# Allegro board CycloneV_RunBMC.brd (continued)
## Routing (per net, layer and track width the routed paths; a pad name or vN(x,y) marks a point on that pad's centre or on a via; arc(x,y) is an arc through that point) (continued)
V_M_BMC_DDR3_DQ<33>: length 39.8
  TOP w0.104: U4.F7 38.61,37.96 38.69,38.04 38.69,38.26 38.58,38.37 v1(37.74,38.37)
  TOP w0.127: UT7.U25 31.56,27.99 v1(31.56,28.01)
  L5-SIG w0.076: v1(31.56,28.01) 31.3,28.01 31.16,28.15 31.15,28.15 30.07,29.23 29.55,29.23 29.43,29.34 29.43,29.88 29.56,30 30.24,30 30.4,29.85 30.4,29.47 30.68,29.19 31.06,29.19 31.18,29.06 31.18,28.67 31.41,28.45 31.79,28.45 31.97,28.63 31.97,29.88 31.84,30 31.29,30 31.16,30.13 31.16,30.36 31.29,30.49 31.92,30.49 32.02,30.59 32.02,30.83 31.91,30.94 31.5,30.94 31.39,31.06 31.39,31.29 31.5,31.4 31.91,31.4 32.02,31.51 32.02,31.74 31.91,31.86 31.64,31.86 31.53,31.97 31.53,32.2 31.64,32.31 31.91,32.31 32.02,32.43 32.02,32.66 31.91,32.77 31.64,32.77 31.53,32.89 31.53,33.11 31.64,33.23 31.91,33.23 32.02,33.34 32.02,33.57 31.91,33.69 31.64,33.69 31.53,33.8 31.53,34.03 31.64,34.14 31.91,34.14 32.02,34.26 32.02,34.63 31.87,34.78 31.57,34.78 31.48,34.86 31.48,35.46 31.59,35.57 32.15,35.57 32.35,35.77 32.35,36.2 32.51,36.35 32.89,36.35 32.97,36.43 32.97,36.62 32.85,36.73 32.06,36.73 31.95,36.85 31.95,37.06 32.06,37.18 32.99,37.18 33.19,37.38 33.19,38.26 33.37,38.44 33.89,38.44 34,38.32 34,36.85 34.12,36.73 34.4,36.73 34.54,36.87 34.54,38.56 34.62,38.64 34.85,38.64 34.93,38.56 34.93,36.98 35.05,36.86 35.24,36.86 35.35,36.98 35.35,38.14 35.46,38.26 35.67,38.26 35.78,38.14 35.78,37.31 35.92,37.17 36.46,37.17 36.57,37.28 36.57,38.07 36.8,38.3 37.28,38.3 37.35,38.37 v1(37.74,38.37)
V_M_BMC_DDR3_DQ<34>: length 34
  TOP w0.127: v1(39.59,30.54) 39.26,30.87 36.3,30.87 35.98,30.54 UT7.AC28 ; U4.F2 v1(41.75,37.57)
  L5-SIG w0.076: v1(39.59,30.54) 39.24,30.89 36.04,30.89 35.93,30.99 35.93,31.25 36.06,31.37 39.82,31.37 40.1,31.65 40.1,32.57 40.71,33.18 40.71,35.16 39.87,36 39.87,36.86 40.3,37.29 40.58,37.29 41.41,36.47 41.64,36.47 41.78,36.61 41.78,36.89 40.76,37.9 40.76,41.83 40.87,41.94 42.02,41.94 42.13,41.83 42.13,41.27 42.02,41.15 41.41,41.15 41.29,41.04 41.29,38.03 v1(41.75,37.57)
V_M_BMC_DDR3_DQ<35>: length 38.9
  TOP w0.127: U4.F8 v1(36.95,37.56) ; v1(32.4,28.01) 32.38,28.01 UT7.V25
  L5-SIG w0.076: v1(36.95,37.56) 37.55,37.56 37.67,37.45 37.67,36.59 37.33,36.25 37.33,34.19 37.1,33.97 36.7,33.97 36.57,34.09 36.57,35.72 36.72,35.87 36.9,35.87 36.98,35.95 36.98,36.28 36.87,36.38 35.96,36.38 35.93,36.4 34.56,36.4 34.36,36.2 34.36,35.54 34.28,35.46 34.03,35.46 33.95,35.54 33.95,36.25 33.8,36.4 33.34,36.4 33.19,36.25 33.19,34.11 33.08,33.99 32.59,33.99 32.48,33.88 32.48,33.67 32.59,33.56 33.08,33.56 33.19,33.44 33.19,33.2 33.11,33.13 32.58,33.13 32.48,33.03 32.48,32.77 32.56,32.7 33.41,32.7 33.52,32.58 33.52,32.39 33.39,32.26 32.59,32.26 32.48,32.15 32.48,31.9 32.62,31.76 33.18,31.76 33.29,31.64 33.29,31.44 33.18,31.32 32.56,31.32 32.48,31.24 32.48,30.93 32.59,30.82 32.63,30.82 32.78,30.66 32.78,28.17 32.79,28.17 32.79,27.85 32.78,27.85 32.78,26.57 32.78,26.57 32.78,26.3 32.48,26 32.26,26 32.05,25.79 30.88,25.79 30.35,26.32 30.35,27.53 30.46,27.64 30.69,27.64 30.8,27.53 30.8,26.88 30.92,26.76 31.08,26.76 31.19,26.88 31.19,27.53 31.31,27.64 31.5,27.64 31.62,27.53 31.62,26.74 31.73,26.62 31.92,26.62 32,26.71 32,27.61 v1(32.4,28.01)
V_M_BMC_DDR3_DQ<36>: length 37.7
  TOP w0.127: U4.H3 v1(41.75,39.16) ; UT7.V19 32.36,23.19 v1(32.4,23.19)
  L5-SIG w0.076: v1(32.4,23.19) 32.77,22.81 33.34,22.81 33.6,23.08 33.6,25.21 34.38,25.99 34.38,26.55 34.68,26.85 34.93,26.85 35.14,27.06 35.14,27.3 35.43,27.59 36.59,27.59 36.75,27.74 36.75,28.22 36.92,28.4 39.59,28.4 39.92,28.73 42.41,28.73 43.77,30.09 43.77,32.89 44.29,33.41 44.29,35.44 45.26,36.4 45.26,41.88 45.14,41.99 44.56,41.99 44.44,42.11 44.44,42.79 44.33,42.91 44.1,42.91 43.98,42.79 43.98,42.11 43.87,41.99 43.06,41.99 42.94,41.88 42.94,40.57 42.72,40.34 42,40.34 41.75,40.08 v1(41.75,39.16)
V_M_BMC_DDR3_DQ<37>: length 37.6
  TOP w0.127: U4.H8 v1(37.75,39.97) ; UT7.V20 32.37,24 32.37,24.05 v1(32.38,24.05)
  L5-SIG w0.076: v1(37.75,39.97) 37.36,39.58 31.54,39.58 31.18,39.22 27.65,39.22 27.53,39.1 27.53,38.91 27.65,38.79 30.35,38.79 30.63,38.51 30.63,31.96 30.12,31.45 29.79,31.45 29.31,30.97 29.31,30.9 29.12,30.71 29.12,30.64 28.8,30.32 28.8,27.77 28.64,27.62 26.59,27.62 26.41,27.44 26.41,26.98 26.64,26.75 28.29,26.75 28.82,26.22 28.82,25.81 29.41,25.23 31.76,25.23 31.87,25.11 31.87,24.56 v1(32.38,24.05)
V_M_BMC_DDR3_DQ<38>: length 33.1
  TOP w0.127: UT7.AE27 v1(37.98,29.61) ; U4.G2 v1(42.55,38.36)
  L5-SIG w0.076: v1(37.98,29.61) 38.37,29.22 39.8,29.22 40.02,29.44 40.02,29.85 40.38,30.21 42.73,30.21 42.91,30.38 42.91,32.71 43.4,33.2 43.5,33.2 43.83,33.54 43.83,36.38 43.95,36.49 44.68,36.49 44.8,36.61 44.8,36.84 44.68,36.95 43.87,36.95 43.76,37.06 43.76,37.29 43.87,37.41 44.68,37.41 44.8,37.52 44.8,37.75 44.68,37.86 43.95,37.86 43.83,37.98 43.83,38.22 43.95,38.33 44.68,38.33 44.8,38.45 44.8,38.7 44.68,38.82 43.92,38.82 43.8,38.93 43.8,39.16 43.92,39.27 44.68,39.27 44.8,39.39 44.8,41.17 44.68,41.28 44.05,41.28 43.94,41.17 43.94,40.19 43.3,39.55 42.26,39.55 42.13,39.43 42.13,38.74 41.95,38.56 41.95,38.06 42.13,37.88 42.13,37.1 42.25,36.99 42.84,36.99 42.94,37.09 42.94,37.97 v1(42.55,38.36)
V_M_BMC_DDR3_DQ<39>: length 33.7
  TOP w0.127: U4.H7 39.53,39.56 39.74,39.35 v1(39.74,39.32) ; UT7.AD28 v1(36.37,30.41)
  L5-SIG w0.076: v1(39.74,39.32) 39.74,39.71 39.63,39.83 39.22,39.83 39.11,39.94 39.11,40.17 39.22,40.28 39.78,40.28 39.9,40.4 39.9,40.63 39.78,40.74 39.07,40.74 38.96,40.86 38.96,41.08 39.07,41.2 39.81,41.2 39.92,41.31 39.92,41.6 39.81,41.71 38.29,41.71 38.14,41.86 38.14,42.11 38.26,42.22 40.28,42.22 40.38,42.12 40.38,37.9 39.52,37.04 39.52,35.87 40.3,35.08 40.3,33.33 39.9,32.92 39.39,32.92 38.83,32.37 35.76,32.37 35.53,32.14 35.53,32.06 35.22,31.76 35.22,29.77 35.2,29.75 35.2,28.31 35.4,28.12 35.78,28.12 35.97,28.31 35.97,28.93 35.96,28.94 35.96,30 v1(36.37,30.41)
V_M_BMC_DDR3_DQS0_N: length 26.1
  TOP w0.127: U2.G3 v1(22.13,38.43) ; UT7.R16 29.91,20.74 29.91,20.79 v1(29.93,20.8)
  L3-SIG w0.076: v1(29.93,20.8) 29.95,20.99 29.88,21.08 29.86,21.09 29.48,21.09 29.46,21.09 28.62,21.92 25.77,21.92 25.51,22.18 25.51,24.41 25.39,24.53 25.39,25.84 24.56,26.68 23.2,26.68 22.3,27.57 22.3,29.45 22.32,29.47 22.32,29.75 21.53,30.54 21.53,30.69 21.47,30.75 21.46,30.75 21.44,30.76
  L3-SIG w0.099: v1(22.13,38.43) 21.91,38.21 21.5,38.21 20.69,37.4 20.69,32.19 21.44,31.44 21.44,30.76
V_M_BMC_DDR3_DQS0_P: length 26.4
  TOP w0.127: UT7.R17 v1(29.99,21.62) ; U2.F3 v1(22.13,37.63)
  L3-SIG w0.076: 21.68,30.76 21.68,30.6 22.47,29.81 22.47,29.4 22.45,29.38 22.45,27.63 23.26,26.83 24.62,26.83 25.55,25.9 25.55,24.59 25.75,24.39 25.75,24.16 25.66,24.07 25.66,23.87 25.77,23.75 25.77,23.48 25.66,23.36 25.66,23.04 25.77,22.93 25.77,22.68 25.66,22.56 25.66,22.24 25.83,22.07 26.2,22.07 26.31,22.18 26.54,22.18 26.64,22.07 26.94,22.07 27.04,22.18 27.3,22.18 27.41,22.07 27.78,22.07 27.89,22.18 28.14,22.18 28.24,22.07 28.83,22.07 28.94,21.96 28.94,21.82 29.1,21.66 29.16,21.66 29.22,21.66 29.36,21.51 29.36,21.46 29.36,21.46 29.36,21.4 29.51,21.25 29.55,21.25 29.92,21.25 29.97,21.3 v1(29.99,21.62)
  L3-SIG w0.099: v1(22.13,37.63) 22.13,37.84 22.02,37.95 21.61,37.95 20.95,37.29 20.95,32.29 21.68,31.56 21.68,30.76
V_M_BMC_DDR3_DQS1_N: length 21.1
  TOP w0.127: v1(29.97,22.4) UT7.R18 ; U2.B7 v1(18.93,34.43)
  L5-SIG w0.076: 25.46,30.76 25.46,30.75 25.5,30.71 25.5,26.95 26.51,25.94 27.81,25.94 29.13,24.62 29.13,23.07 29.49,22.71 29.66,22.71 29.66,22.71 v1(29.97,22.4)
  L5-SIG w0.094: v1(18.93,34.43) 19.21,34.71 19.38,34.71 19.5,34.58 19.5,34.07 22.1,31.48 25.2,31.48 25.46,31.21 25.46,30.76
V_M_BMC_DDR3_DQS1_P: length 21.3
  TOP w0.127: v1(29.97,23.16) 29.62,22.81 UT7.R19 ; U2.C7 v1(18.93,35.23)
  L5-SIG w0.076: v1(29.97,23.16) 29.97,22.97 29.86,22.86 29.65,22.86 29.55,22.86 29.28,23.13 29.28,24.68 27.87,26.09 26.57,26.09 25.66,27.01 25.66,30.71 25.69,30.75 25.69,30.76
  L5-SIG w0.094: v1(18.93,35.23) 19.22,34.93 19.47,34.93 19.73,34.68 19.73,34.17 22.19,31.7 25.3,31.7 25.69,31.31 25.69,30.76
V_M_BMC_DDR3_DQS2_N: length 27.3
  TOP w0.127: U3.G3 v1(31.19,38.43) ; UT7.T18 v1(30.78,22.41)
  L10-SIG w0.076: v1(30.78,22.41) 30.78,22.49 30.63,22.64 30.51,22.64 30.32,22.83 30.32,23.3 30.12,23.5 29.52,23.5 29.29,23.73 29.29,23.8
  L10-SIG w0.099: 29.29,23.8 29.29,33.49 29.57,33.78 31.37,33.78 31.51,33.91 31.51,34.3 31.4,34.41 29.49,34.41 29.23,34.67 29.23,35.11 29.49,35.37 31.25,35.37 31.36,35.48 31.36,35.7 31.25,35.82 29.62,35.82 29.36,36.08 29.36,36.51 29.62,36.77 30.06,36.77 30.17,36.88 30.17,38.01 30.47,38.31 31.08,38.31 v1(31.19,38.43)
V_M_BMC_DDR3_DQS2_P: length 28.1
  TOP w0.127: UT7.T19 v1(30.78,23.21) ; U3.F3 v1(31.19,37.63)
  L10-SIG w0.076: v1(30.78,23.21) 30.78,22.89 30.68,22.79 30.57,22.79 30.47,22.89 30.47,23.44 30.26,23.65 29.58,23.65 29.54,23.7 29.54,23.8
  L10-SIG w0.099: v1(31.19,37.63) 31.19,37.89 31.03,38.05 30.57,38.05 30.42,37.9 30.42,36.78 30.16,36.52 29.72,36.52 29.61,36.4 29.61,36.18 29.72,36.07 31.36,36.07 31.62,35.81 31.62,35.37 31.36,35.11 29.59,35.11 29.48,35 29.48,34.78 29.59,34.67 31.5,34.67 31.76,34.41 31.76,33.81 31.48,33.52 29.68,33.52 29.54,33.38 29.54,31.22 29.71,31.04 29.71,30.69 29.54,30.52 29.54,30.22 29.66,30.1 29.66,29.87 29.54,29.75 29.54,29.44 29.66,29.32 29.66,29.04 29.54,28.92 29.54,28.65 29.66,28.53 29.66,28.29 29.54,28.17 29.54,27.84 29.71,27.67 29.71,27.49 29.54,27.32 29.54,27.05 29.66,26.93 29.66,26.65 29.54,26.53 29.54,25.73 29.71,25.56 29.71,25.25 29.54,25.08 29.54,24.79 29.74,24.59 29.74,24.31 29.54,24.12 29.54,23.8
V_M_BMC_DDR3_DQS3_N: length 29.9
  TOP w0.119: U3.B7 v1(28.91,35.34)
  TOP w0.127: UT7.T20 v1(30.78,24.01)
  L3-SIG w0.076: v1(30.78,24.01) 30.78,23.63 30.85,23.55 31.01,23.55 31.08,23.63 31.08,24.39 31.23,24.54 31.39,24.54 31.52,24.66 31.52,24.83 31.66,24.97 31.83,24.97 31.9,25.04 31.9,25.2 31.82,25.28 31.27,25.28 31.11,25.44 31.11,25.8 31.27,25.96 31.71,25.96 31.83,26.09 31.83,26.74 31.72,26.85 31.28,26.85 31.09,27.04 31.09,27.28 31.43,27.62 31.82,27.62 31.9,27.69 31.9,30.51 31.74,30.67 31.53,30.67
  L3-SIG w0.099: v1(28.91,35.34) 28.91,35.65 28.99,35.73 29.44,35.73 29.84,36.12 30.47,36.12 30.6,36 31.25,36 31.36,35.89 31.36,35.5 31.23,35.36 29.57,35.36 29.31,35.1 29.31,34.56 29.57,34.3 31.61,34.3 31.72,34.18 31.72,33.83 31.61,33.72 30.15,33.72 29.89,33.46 29.89,32.77 30.15,32.51 31.93,32.51 32.05,32.39 32.05,32.06 31.93,31.94 30.96,31.94 30.65,31.63 30.65,31.05 31.02,30.67 31.53,30.67
V_M_BMC_DDR3_DQS3_P: length 29.5
  TOP w0.127: U3.C7 28.87,36.1 v1(28.9,36.1) ; v1(31.56,23.21) 31.56,23.19 UT7.U19
  L3-SIG w0.076: 31.96,30.76 32.05,30.67 32.05,27.63 31.89,27.46 31.49,27.46 31.24,27.21 31.24,27.1 31.34,27.01 31.78,27.01 31.98,26.8 31.98,26.03 31.77,25.81 31.34,25.81 31.26,25.74 31.26,25.51 31.34,25.43 31.89,25.43 32.05,25.27 32.05,24.98 31.24,24.16 31.24,23.53 v1(31.56,23.21)
  L3-SIG w0.099: 31.96,30.76 31.8,30.93 31.13,30.93 30.91,31.15 30.91,31.53 31.07,31.69 32.03,31.69 32.3,31.96 32.3,32.49 32.03,32.76 30.25,32.76 30.14,32.87 30.14,33.35 30.25,33.46 31.71,33.46 31.97,33.72 31.97,34.29 31.71,34.55 29.68,34.55 29.56,34.66 29.56,35 29.68,35.11 31.33,35.11 31.62,35.39 31.62,35.99 31.36,36.25 30.71,36.25 30.58,36.38 29.73,36.38 29.34,35.98 29.06,35.98 28.95,36.1 v1(28.9,36.1)
V_M_BMC_DDR3_DQS4_N: length 37.7
  TOP w0.127: v1(39.77,38.76) 40.02,38.51 41.1,38.51 U4.G3 ; UT7.V17 v1(32.38,21.61)
  L5-SIG w0.076: v1(32.38,21.61) 32.34,21.61 31.9,22.05 31.9,23.52 32.07,23.68 32.49,23.68 32.72,23.91 32.72,25.26 33.5,26.04 33.5,26.9 33.5,26.91 33.5,29.37 33.71,29.58 34.18,29.58 34.26,29.66 34.26,29.81 34.18,29.89 33.66,29.89 33.5,30.05 33.5,30.71 33.46,30.75 33.46,30.76
  L5-SIG w0.094: 33.46,30.76 33.46,30.95 34.82,32.31 34.82,32.56 34.69,32.68 34.19,32.68 33.93,32.94 33.93,33.36 34.19,33.62 34.69,33.62 34.82,33.75 34.82,33.99 34.69,34.11 34.29,34.11 34.03,34.37 34.03,34.8 34.29,35.06 34.69,35.06 34.82,35.18 34.82,35.68 35.07,35.94 35.48,35.94 35.73,35.68 35.73,33.42 35.98,33.18 37.68,33.18 37.68,33.18 38.05,33.18 38.17,33.3 38.17,33.7 38.43,33.95 39.5,33.95 39.62,34.08 39.62,34.32 39.5,34.44 38.43,34.44 38.17,34.7 38.17,35.13 38.43,35.39 38.71,35.39 38.83,35.51 38.83,35.75 38.71,35.87 38.43,35.87 38.17,36.13 38.17,37.92 38.71,38.46 39.47,38.46 v1(39.77,38.76)
V_M_BMC_DDR3_DQS4_P: length 37.6
  TOP w0.127: U4.F3 41.06,38.25 40.05,38.25 v1(39.77,37.96) ; UT7.V18 v1(32.38,22.41)
  L5-SIG w0.076: v1(32.38,22.41) 32.38,22.15 32.28,22.05 32.11,22.05 32.05,22.11 32.05,22.62 32.15,22.71 32.15,22.92 32.05,23.02 32.05,23.45 32.13,23.53 32.56,23.53 32.87,23.85 32.87,24.22 32.99,24.34 32.99,24.57 32.87,24.68 32.87,25.2 33.05,25.38 33.22,25.38 33.37,25.53 33.37,25.7 33.65,25.98 33.65,26.68 33.75,26.77 33.75,27 33.65,27.1 33.65,29.31 33.78,29.43 34.25,29.43 34.41,29.6 34.41,29.88 34.25,30.04 33.73,30.04 33.65,30.12 33.65,30.71 33.69,30.75 33.69,30.76
  L5-SIG w0.094: v1(39.77,37.96) 39.77,38.05 39.59,38.23 38.8,38.23 38.4,37.83 38.4,36.22 38.52,36.1 38.8,36.1 39.06,35.85 39.06,35.41 38.8,35.16 38.52,35.16 38.4,35.04 38.4,34.79 38.52,34.67 39.59,34.67 39.85,34.41 39.85,33.98 39.59,33.73 38.52,33.73 38.4,33.6 38.4,33.2 38.14,32.95 37.59,32.95 37.58,32.95 35.88,32.95 35.5,33.33 35.5,35.59 35.38,35.71 35.17,35.71 35.05,35.59 35.05,35.08 34.79,34.83 34.38,34.83 34.26,34.71 34.26,34.46 34.38,34.34 34.79,34.34 35.05,34.08 35.05,33.65 34.79,33.39 34.29,33.39 34.16,33.26 34.16,33.04 34.29,32.91 34.79,32.91 35.05,32.65 35.05,32.21 33.69,30.86 33.69,30.76
V_M_BMC_DDR3_MA<0>: length 51.6
  TOP w0.127: U3.N3 v1(31.97,44.01) ; v1(19.6,30.71) 19.6,30.38 UT7.C28 ; U4.N3 v1(41.75,43.96) ; U2.N3 v1(22.13,44.03)
  L8-SIG w0.076: v1(19.6,30.71) 19.6,31.1 19.42,31.28 19.42,31.88 20.52,32.97 20.52,33.49 20.4,33.61 19.87,33.61 19.75,33.72 19.75,33.95 19.87,34.06 20.4,34.06 20.52,34.18 20.52,34.41 20.4,34.52 19.87,34.52 19.75,34.64 19.75,34.86 19.87,34.98 20.4,34.98 20.52,35.09 20.52,35.32 20.4,35.44 19.87,35.44 19.75,35.55 19.75,35.78 19.87,35.89 20.4,35.89 20.52,36.01 20.52,36.43 20.63,36.54 20.83,36.54 20.95,36.65 20.95,36.88 20.83,37 20.63,37 20.52,37.11 20.52,37.34 20.63,37.45 20.99,37.45 21.1,37.57 21.1,37.8 20.99,37.91 20.63,37.91 20.52,38.03 20.52,38.25 20.63,38.37 21.11,38.37 21.23,38.48 21.23,38.71 21.11,38.83 20.63,38.83 20.52,38.94 20.52,39.17 20.63,39.28 21.11,39.28 21.23,39.4 21.23,39.63 21.11,39.74 20.63,39.74 20.52,39.85 20.52,40.08 20.63,40.2 20.83,40.2 20.95,40.31 20.95,40.54 20.83,40.65 20.63,40.65 20.52,40.77 20.52,41 20.63,41.11 20.73,41.11 20.85,41.23 20.85,41.45 20.73,41.57 20.63,41.57 20.52,41.68 20.52,41.91 20.63,42.03 20.71,42.03 20.82,42.14 20.82,42.37 20.71,42.48 20.63,42.48 20.52,42.6 20.52,43.72 20.95,44.15 22,44.15 v1(22.13,44.03) 22.55,43.6 23.88,43.6 23.89,43.59 31.56,43.59 v1(31.97,44.01) 32.39,43.59 41.37,43.59 v1(41.75,43.96)
  BOTTOM w0.112: RB4.1 41.62,47.58 41.16,47.12 41.16,44.55 v1(41.75,43.96)
V_M_BMC_DDR3_MA<1>: length 51.3
  TOP w0.127: U2.P7 v1(18.13,44.83) ; UT7.B28 18.78,30.41 18.78,30.68 v1(18.77,30.69) ; U3.P7 v1(27.97,44.81) ; U4.P7 v1(37.75,44.76)
  L10-SIG w0.076: v1(37.75,44.76) 37.34,44.35 33.74,44.35 33.72,44.37 31.82,44.37 31.81,44.35 28.42,44.35 v1(27.97,44.81) 27.56,44.39 19.49,44.39 19.05,44.83 v1(18.13,44.83) 18.13,44.83 17.84,44.83 17.42,45.24 16.35,45.24 15.51,44.4 15.51,40.16 15.97,39.71 18.31,39.71 18.51,39.5 18.51,37.3 18.6,37.21 20.12,37.21 20.21,37.12 20.21,36.94 20.12,36.85 18.6,36.85 18.51,36.76 18.51,33.85 18.77,33.59 18.77,33.37 18.86,33.28 19.23,33.28 19.32,33.2 19.32,33.02 19.23,32.93 18.86,32.93 18.69,32.76 18.69,30.77 v1(18.77,30.69)
  BOTTOM w0.112: RB12.1 37.05,47.91 37.7,47.26 38.06,47.26 38.57,46.75 38.59,46.75 38.8,46.54 38.8,45.82 v1(37.75,44.76)
V_M_BMC_DDR3_MA<2>: length 52.6
  TOP w0.127: U2.P3 v1(22.13,44.83) ; UT7.E26 v1(21.18,28.81) ; U4.P3 v1(41.75,44.76) ; U3.P3 v1(31.97,44.81)
  L8-SIG w0.076: v1(21.18,28.81) 20.98,28.81 20.54,29.24 20.11,29.24 19.96,29.39 19.96,29.95 19.75,30.16 19.36,30.16 19.14,30.37 19.14,30.89 18.87,31.17 18.87,32.77 19.37,33.28 19.37,36.77 19.49,36.88 19.92,36.88 20.03,37 20.03,37.23 19.92,37.34 19.69,37.34 19.58,37.45 19.58,37.68 19.69,37.8 19.92,37.8 20.03,37.91 20.03,38.14 19.92,38.25 19.44,38.25 19.32,38.37 19.32,38.6 19.44,38.71 19.92,38.71 20.03,38.83 20.03,39.05 19.92,39.17 19.41,39.17 19.3,39.28 19.3,39.51 19.41,39.63 19.92,39.63 20.03,39.74 20.03,39.97 19.92,40.08 19.28,40.08 19.17,40.2 19.17,40.43 19.28,40.54 19.92,40.54 20.03,40.65 20.03,40.88 19.92,41 19.56,41 19.45,41.11 19.45,41.34 19.56,41.45 19.92,41.45 20.03,41.57 20.03,41.8 19.92,41.91 19.69,41.91 19.58,42.03 19.58,42.25 19.69,42.37 19.92,42.37 20.03,42.48 20.03,42.71 19.92,42.83 19.69,42.83 19.58,42.94 19.58,43.26 21.14,44.83 v1(22.13,44.83) 22.52,44.43 31.6,44.43 v1(31.97,44.81) 32.4,44.38 41.4,44.38 41.75,44.73 v1(41.75,44.76)
  BOTTOM w0.112: v1(41.75,44.76) 41.39,45.12 41.39,45.41 41.39,45.41 41.39,46.89 42.13,47.63 RB3.1
V_M_BMC_DDR3_MA<3>: length 49.7
  TOP w0.127: U2.N2 v1(22.93,44.03) ; U3.N2 v1(32.77,44.01) ; UT7.D26 v1(20.38,28.81) ; U4.N2 v1(42.55,43.96)
  L3-SIG w0.076: v1(42.55,43.96) 42.16,44.35 33.12,44.35 v1(32.77,44.01) 32.4,44.38 23.28,44.38 v1(22.93,44.03)
  BOTTOM w0.112: v1(20.38,28.81) 20.75,29.17 20.75,30.18 20.49,30.43 20.49,31.76 20.95,32.21 20.95,33.31 20.79,33.46 19.99,33.46 19.88,33.57 19.88,33.77 19.99,33.88 20.79,33.88 20.9,33.98 20.9,34.19 20.79,34.3 19.99,34.3 19.88,34.4 19.88,34.61 19.99,34.71 20.79,34.71 20.9,34.82 20.9,39.06 21,39.17 21.28,39.17 21.38,39.27 21.38,39.48 21.28,39.58 20.82,39.58 20.72,39.69 20.72,39.9 20.82,40 21.28,40 21.38,40.1 21.38,40.31 21.28,40.42 20.82,40.42 20.72,40.52 20.72,40.73 20.82,40.83 21.28,40.83 21.38,40.94 21.38,41.15 21.28,41.25 20.87,41.25 20.77,41.35 20.77,41.56 20.87,41.67 21.28,41.67 21.38,41.77 21.38,41.98 21.28,42.08 21,42.08 20.9,42.19 20.9,43.41 21.1,43.62 22.52,43.62 v1(22.93,44.03) ; v1(42.55,43.96) 42.92,43.59 43.14,43.59 43.17,43.57 RB37.1
V_M_BMC_DDR3_MA<4>: length 56.3
  TOP w0.127: U2.P8 v1(17.33,44.83) ; U4.P8 v1(36.95,44.76) ; U3.P8 v1(27.17,44.81) ; UT7.J21 v1(24.38,24.81)
  L5-SIG w0.076: v1(24.38,24.81) 24.29,24.81 23.9,25.2 18.61,25.2 17.73,26.09 17.72,26.09 17.51,26.3 17.51,26.3 14.73,29.09 14.73,42.96 16.23,44.47 16.96,44.47 v1(17.33,44.83) 17.72,44.43 26.8,44.43 v1(27.17,44.81)
  L5-SIG w0.114: v1(27.17,44.81) 27.53,44.44 35.72,44.44 35.76,44.4 36.59,44.4 v1(36.95,44.76)
  BOTTOM w0.112: RB17.1 34,47.4 34.79,46.61 34.79,45.9 35.34,45.34 35.34,45.34 35.43,45.25 35.44,45.25 35.5,45.18 36.53,45.18 v1(36.95,44.76)
V_M_BMC_DDR3_MA<5>: length 51.1
  TOP w0.127: UT7.J20 v1(24.38,24.01) ; U2.P2 v1(22.93,44.83) ; U4.P2 v1(42.55,44.76) ; U3.P2 v1(32.77,44.81)
  L5-SIG w0.076: v1(22.93,44.83) 23.34,45.24 32.33,45.24 v1(32.77,44.81) 33.21,45.24 35.96,45.24 36,45.2 42.11,45.2 v1(42.55,44.76)
  BOTTOM w0.112: v1(42.55,44.76) 42.94,45.16 44.07,45.16 44.57,44.66 RB32.1 ; v1(24.38,24.01) 24,24.39 24,26.09 23.08,27.01 23.08,27.67 23.18,27.77 23.18,29.19 21.38,30.99 21.38,32.21 21.81,32.64 22.75,32.64 22.85,32.75 22.85,32.96 22.75,33.06 21.81,33.06 21.71,33.16 21.71,42.6 21.96,42.86 23.16,42.86 23.31,43.01 23.31,44.44 v1(22.93,44.83)
V_M_BMC_DDR3_MA<6>: length 50.6
  TOP w0.127: U4.R8 v1(36.95,45.56) ; U3.R8 v1(27.17,45.61) ; UT7.C26 v1(19.58,28.81) ; U2.R8 v1(17.33,45.63)
  L10-SIG w0.076: v1(36.95,45.56) 36.59,45.2 27.58,45.2 v1(27.17,45.61) 26.76,45.19 21.87,45.19 21.81,45.24 17.87,45.24 17.49,45.63 v1(17.33,45.63) 16.96,45.99 16.13,45.99 15.13,44.99 15.13,39.81 16.07,38.87 17.65,38.87 17.77,38.74 17.77,38.47 17.68,38.38 17.02,38.38 16.94,38.29 16.94,38.11 17.02,38.02 17.68,38.02 17.77,37.93 17.77,29.55 18.1,29.22 19.48,29.22 19.58,29.11 v1(19.58,28.81)
  BOTTOM w0.112: RB16.1 34.51,47.53 35.32,46.73 36.3,46.73 36.57,46.45 36.57,45.94 v1(36.95,45.56)
V_M_BMC_DDR3_MA<7>: length 51.1
  TOP w0.127: UT7.B26 18.8,28.79 v1(18.8,28.83) ; U3.R2 v1(32.77,45.61) ; U4.R2 v1(42.55,45.56) ; U2.R2 v1(22.93,45.63)
  L8-SIG w0.076: v1(42.55,45.56) 42.17,45.19 33.19,45.19 v1(32.77,45.61) 32.4,45.23 23.32,45.23 v1(22.93,45.63) 22.54,45.24 19.78,45.24 19.28,44.75 19.28,44.59 19.72,44.15 19.72,43.99 19.56,43.83 19.4,43.83 18.96,44.26 18.8,44.26 18.51,43.97 18.51,42.07 18.4,41.95 18.09,41.95 17.98,41.84 17.98,41.61 18.09,41.49 18.4,41.49 18.51,41.38 18.51,41.15 18.4,41.04 18.09,41.04 17.98,40.92 17.98,40.69 18.09,40.58 18.4,40.58 18.51,40.47 18.51,34.09 18.84,33.76 18.84,33.53 18.33,33.03 18.33,30.46 18.61,30.18 18.84,30.18 19.2,29.83 19.2,29.01 19.01,28.83 v1(18.8,28.83)
  BOTTOM w0.112: v1(42.55,45.56) 42.97,45.98 42.97,46.49 42.99,46.51 42.99,46.51 43.2,46.73 43.2,46.73 43.25,46.77 43.95,46.77 44.11,46.61 44.11,45.88 44.8,45.19 RB30.1
V_M_BMC_DDR3_MA<8>: length 56
  TOP w0.127: U3.T8 v1(27.17,46.41) ; UT7.F26 21.98,28.81 v1(21.96,28.81) ; U4.T8 v1(36.95,46.36) ; U2.T8 v1(17.33,46.43)
  L10-SIG w0.076: v1(21.96,28.81) 21.6,28.45 17.12,28.45 16.76,28.81 16.76,29.72 17.37,30.33 17.37,36.91 17.04,37.24 14.9,37.24 14.78,37.37 14.78,38 14.87,38.09 15.58,38.09 15.67,38.18 15.67,38.36 15.58,38.45 14.87,38.45 14.78,38.53 14.78,38.71 14.87,38.8 15.25,38.8 15.33,38.89 15.33,39.07 15.25,39.16 14.87,39.16 14.78,39.25 14.78,45.34 16.33,46.89 16.86,46.89 v1(17.33,46.43) 17.75,46 26.77,46 v1(27.17,46.41) 27.61,45.97 36.55,45.97 v1(36.95,46.36)
  BOTTOM w0.112: v1(36.95,46.36) 36.95,46.46 36.47,46.94 35.74,46.94 35.02,47.66 RB15.1
V_M_BMC_DDR3_MA<9>: length 55.6
  TOP w0.127: UT7.F25 v1(21.96,28.03) ; U2.R3 v1(22.13,45.63) ; U4.R3 v1(41.75,45.56) ; U3.R3 v1(31.97,45.61)
  L8-SIG w0.076: v1(21.96,28.03) 21.58,28.4 19.97,28.4 19.86,28.29 19.86,27.9 19.76,27.8 19.42,27.8 19.32,27.9 19.32,28.29 19.21,28.4 18.56,28.4 18.36,28.61 18.36,29.75 17.89,30.22 17.89,33.04 17.72,33.2 17.72,34.18 17.61,34.3 17.41,34.3 17.29,34.41 17.29,34.64 17.41,34.75 17.66,34.75 17.77,34.87 17.77,35.1 17.66,35.21 17.41,35.21 17.29,35.32 17.29,35.55 17.41,35.67 17.61,35.67 17.72,35.78 17.72,36.01 17.61,36.12 17.41,36.12 17.29,36.24 17.29,36.47 17.41,36.58 17.61,36.58 17.72,36.7 17.72,36.92 17.61,37.04 17.41,37.04 17.29,37.15 17.29,37.38 17.41,37.5 17.61,37.5 17.72,37.61 17.72,37.84 17.61,37.95 17.41,37.95 17.29,38.07 17.29,38.3 17.41,38.41 17.61,38.41 17.72,38.52 17.72,38.75 17.61,38.87 17.41,38.87 17.29,38.98 17.29,39.21 17.41,39.32 17.61,39.32 17.72,39.44 17.72,39.67 17.61,39.78 17.41,39.78 17.29,39.9 17.29,40.12 17.41,40.24 17.61,40.24 17.72,40.35 17.72,44.18 17.98,44.43 18.38,44.43 19.58,45.63 v1(22.13,45.63) 22.5,46 31.57,46 v1(31.97,45.61) 32.37,46 35.99,46 36,46 41.31,46 v1(41.75,45.56)
  BOTTOM w0.112: v1(41.75,45.56) 42.13,45.95 42.13,46.51 43.27,47.66 RB1.1
V_M_BMC_DDR3_MA<10>: length 52.6
  TOP w0.127: U2.L7 v1(18.13,42.43) ; U3.L7 v1(27.97,42.41) ; U4.L7 v1(37.75,42.36) ; UT7.A24 v1(17.98,27.21)
  L5-SIG w0.076: v1(18.13,42.43) 21.43,42.43 21.81,42.04 27.61,42.04 v1(27.97,42.41) 28.46,42.41 28.87,41.99 37.38,41.99 v1(37.75,42.36)
  BOTTOM w0.112: RB8.1 39.08,47.61 39.62,47.07 39.62,46.93 39.68,46.87 39.68,43.5 38.54,42.36 v1(37.75,42.36) ; v1(17.98,27.21) 17.54,27.64 17.54,29.01 17.98,29.44 17.98,30.64 17.72,30.89 17.72,32.13 17.62,32.23 17.24,32.23 17.14,32.33 17.14,32.54 17.24,32.65 17.62,32.65 17.72,32.75 17.72,32.96 17.62,33.06 17.24,33.06 17.14,33.17 17.14,33.38 17.24,33.48 17.62,33.48 17.72,33.58 17.72,37.08 17.86,37.22 19.45,37.22 19.55,37.32 19.55,39.8 19.45,39.9 18.39,39.9 18.28,40.01 18.28,40.21 18.39,40.32 19.45,40.32 19.55,40.42 19.55,42.19 19.14,42.6 18.3,42.6 v1(18.13,42.43)
V_M_BMC_DDR3_MA<11>: length 49.6
  TOP w0.127: U4.R7 v1(37.75,45.56) ; UT7.B24 v1(18.78,27.21) ; U2.R7 v1(18.13,45.63) ; U3.R7 v1(27.97,45.61)
  L3-SIG w0.076: v1(37.75,45.56) 37.4,45.22 37.09,45.22 37.09,45.22 36,45.22 36,45.22 28.36,45.22 v1(27.97,45.61) 27.62,45.26 21.87,45.26 21.5,45.63 v1(18.13,45.63)
  BOTTOM w0.112: v1(37.75,45.56) 37.33,45.98 37.33,46.48 37.31,46.5 37.31,46.51 37.1,46.73 36.99,46.73 36.56,47.15 36.01,47.15 35.53,47.63 RB14.1 ; v1(18.13,45.63) 18.22,45.73 19.7,45.73 19.91,45.52 19.91,45.28 19.8,45.18 19.3,45.18 19.2,45.07 19.2,44.86 19.3,44.76 19.8,44.76 19.91,44.66 19.91,44.45 19.8,44.34 19.58,44.34 19.48,44.24 19.48,44.03 19.58,43.93 19.8,43.93 19.91,43.82 19.91,37.14 19.53,36.76 18.69,36.76 18.54,36.61 18.54,33.43 18.36,33.25 18.36,27.63 v1(18.78,27.21)
V_M_BMC_DDR3_MA<12>: length 56.1
  TOP w0.127: v1(20.38,27.19) 20.4,27.19 UT7.D24 ; U4.N7 v1(37.75,43.96) ; U2.N7 v1(18.13,44.03) ; U3.N7 v1(27.97,44.01)
  L3-SIG w0.076: v1(20.38,27.19) 20.44,27.25 20.44,27.59 20.73,27.88 20.73,28.97 20.53,29.17 19.33,29.17 19.17,29.01 19.17,28.53 19.04,28.4 18.66,28.4 18.38,28.12 18.38,27.84 18.15,27.62 17.19,27.62 16.83,27.97 16.83,29.58 16.66,29.75 16.66,29.75 16.58,29.83 16.58,30.94 16.1,31.43 16.1,32.8 15.31,33.58 15.31,35.78 15.4,35.87 15.73,35.87 15.82,35.96 15.82,36.14 15.73,36.23 15.4,36.23 15.31,36.31 15.31,36.49 15.4,36.58 15.73,36.58 15.82,36.67 15.82,36.85 15.73,36.94 15.4,36.94 15.31,37.03 15.31,37.2 15.4,37.29 15.73,37.29 15.82,37.38 15.82,37.56 15.73,37.65 15.4,37.65 15.31,37.74 15.31,42.7 16.2,43.59 17.69,43.59 v1(18.13,44.03) 21.55,44.03 21.94,43.64 27.61,43.64 v1(27.97,44.01) 31.23,44.01 31.64,43.59 37.38,43.59 v1(37.75,43.96)
  BOTTOM w0.112: RB10.1 38.07,47.9 38.36,47.6 38.36,47.59 39.19,46.76 39.19,46.75 39.23,46.72 39.23,45.23 37.96,43.96 v1(37.75,43.96)
V_M_BMC_DDR3_MA<13>: length 52
  TOP w0.127: U3.T3 v1(31.97,46.41) ; U4.T3 v1(41.75,46.36) ; U2.T3 v1(22.13,46.43) ; UT7.C24 v1(19.58,27.21)
  L5-SIG w0.076: v1(41.75,46.36) 41.36,45.98 32.4,45.98 v1(31.97,46.41) 31.6,46.03 22.52,46.03 v1(22.13,46.43)
  L8-SIG w0.076: v1(19.58,27.21) 19.2,27.59 17.72,27.59 17.01,28.3 17.01,29.67 17.44,30.1 17.44,32.8 16.93,33.31 16.93,45.09 17.06,45.22 18.48,45.22 19.69,46.43 20.28,46.43 20.36,46.35 20.36,46.06 20.43,45.98 20.59,45.98 20.66,46.06 20.66,46.35 20.74,46.43 20.89,46.43 20.97,46.35 20.97,46.06 21.04,45.98 21.2,45.98 21.27,46.06 21.27,46.35 21.35,46.43 v1(22.13,46.43)
  BOTTOM w0.112: RB2.1 42.64,47.61 41.75,46.71 v1(41.75,46.36)
V_M_BMC_DDR3_MA<14>: length 55.6
  TOP w0.127: U4.T7 v1(37.75,46.36) ; U3.T7 v1(27.97,46.41) ; U2.T7 v1(18.13,46.43) ; UT7.G23 v1(23.58,25.6)
  L3-SIG w0.076: v1(18.13,46.43) 18.5,46.06 27.62,46.06 v1(27.97,46.41) 28.36,46.02 37.4,46.02 v1(37.75,46.36)
  BOTTOM w0.112: v1(37.75,46.36) 37.52,46.59 37.52,46.6 36.78,47.35 36.69,47.35 36.67,47.37 36.37,47.37 36.04,47.7 RB13.1 ; v1(18.13,46.43) 18.52,46.82 19.84,46.82 20.34,46.32 20.34,36.96 19.35,35.97 19.35,35.74 19.45,35.64 20.01,35.64 20.11,35.53 20.11,35.32 20.01,35.22 19.45,35.22 19.35,35.12 19.35,33.91 19.02,33.58 19.02,33.01 19.12,32.9 19.52,32.9 19.63,32.8 19.63,32.59 19.52,32.49 19.12,32.49 19.02,32.38 19.02,32.18 19.12,32.07 19.5,32.07 19.6,31.97 19.6,31.76 19.5,31.65 19.12,31.65 19.02,31.55 19.02,31.21 19.12,31.11 19.77,31.11 19.98,30.89 19.98,28.56 20.14,28.4 22.19,28.4 22.35,28.25 22.35,27.34 23.58,26.1 v1(23.58,25.6)
V_M_BMC_DDR3_MA<15>: length 59.8
  TOP w0.127: UT7.F24 22,27.19 v1(21.96,27.19) ; v1(38.55,43.19) 38.55,43.16 U4.M7 ; U3.M7 v1(28.77,43.21) ; U2.M7 v1(18.93,43.23)
  L10-SIG w0.076: v1(38.55,43.19) 38.13,42.77 31.82,42.77 31.76,42.7 29.27,42.7 v1(28.77,43.21) 28.4,42.83 19.32,42.83 v1(18.93,43.23) 18.56,43.59 17.43,43.59 17.35,43.5 17.35,43.27 17.26,43.19 17.08,43.19 16.99,43.27 16.99,43.5 16.9,43.59 16.35,43.59 16.15,43.39 16.15,40.65 16.38,40.42 17.68,40.42 17.76,40.51 17.76,40.86 17.85,40.95 18.03,40.95 18.12,40.86 18.12,40.51 18.21,40.42 19.35,40.42 19.44,40.51 19.44,40.79 19.53,40.87 19.71,40.87 19.8,40.79 19.8,40.51 19.89,40.42 20.82,40.42 20.92,40.32 20.92,31.73 21.23,31.43 23.84,31.43 24.02,31.25 24.02,26.75 23.89,26.62 23.29,26.62 23.08,26.83 22.32,26.83 v1(21.96,27.19)
  BOTTOM w0.112: v1(38.55,43.19) 38.55,43.96 39.44,44.86 39.44,46.81 39.41,46.84 39.41,46.85 38.58,47.68 RB9.1
V_M_BMC_DDR3_ODT: length 47.7
  TOP w0.127: UT7.D28 20.78,30.49 v1(21,30.71) ; U3.K1 v1(33.57,41.61) ; U2.K1 v1(23.73,41.63) ; U4.K1 v1(43.35,41.56)
  L8-SIG w0.076: v1(43.35,41.56) 42.94,41.15 34.02,41.15 v1(33.57,41.61) 33.15,41.18 25.06,41.18 24.61,41.63 v1(23.73,41.63) 24.2,41.15 24.2,40.34 24.78,39.76 24.78,39.52 24.9,39.4 25.69,39.4 25.8,39.29 25.8,39.06 25.69,38.94 24.9,38.94 24.78,38.83 24.78,38.6 24.9,38.49 25.69,38.49 25.8,38.37 25.8,38.14 25.69,38.03 24.9,38.03 24.78,37.92 24.78,37.69 24.9,37.57 25.69,37.57 25.8,37.46 25.8,37.23 25.69,37.11 24.9,37.11 24.78,37 24.78,35.26 24.67,35.14 24.2,35.14 24.09,35.03 24.09,34.8 24.2,34.69 24.67,34.69 24.78,34.57 24.78,34.34 24.67,34.23 24.2,34.23 24.09,34.11 24.09,33.89 24.2,33.77 24.67,33.77 24.78,33.66 24.78,33.43 24.67,33.31 24.2,33.31 24.09,33.2 24.09,32.97 24.2,32.86 24.67,32.86 24.78,32.74 24.78,31.58 24.66,31.45 21.63,31.45 21,30.82 v1(21,30.71)
  BOTTOM w0.112: RB41.1 44.03,41.86 43.73,41.56 v1(43.35,41.56)
V_M_BMC_DDR3_RAS_N: length 50.8
  TOP w0.127: U3.J3 v1(31.97,40.81) ; UT7.A25 18,27.99 v1(17.98,27.99) ; U4.J3 v1(41.75,40.76) ; U2.J3 v1(22.13,40.83)
  L3-SIG w0.076: v1(17.98,27.99) 17.33,27.99 17.19,28.12 17.19,28.34 17.28,28.43 18.24,28.43 18.33,28.52 18.33,29.49 17.98,29.85 17.98,29.98 17.67,30.28 17.67,32.29 17.57,32.39 17.57,38.97 17.24,39.3 17.24,40.3 17.1,40.44 17.05,40.44 16.96,40.53 16.96,41.14 17.05,41.23 17.68,41.23 17.76,41.14 17.76,40.91 17.85,40.82 18.03,40.82 18.12,40.91 18.12,41.14 18.21,41.23 19.47,41.23 19.55,41.14 19.55,40.99 19.64,40.9 19.82,40.9 19.91,40.99 19.91,41.37 20,41.46 20.29,41.46 20.38,41.37 20.38,40.91 20.47,40.82 20.64,40.82 20.73,40.91 20.73,41.45 20.82,41.53 21,41.53 21.09,41.45 21.09,40.91 21.18,40.82 21.36,40.82 21.44,40.91 21.44,41.5 21.51,41.56 21.68,41.56 21.76,41.48 21.76,40.92 21.81,40.87 22.08,40.87 v1(22.13,40.83) 22.5,41.2 31.58,41.2 v1(31.97,40.81) 32.35,41.18 41.33,41.18 v1(41.75,40.76)
  BOTTOM w0.112: v1(41.75,40.76) 42.16,41.18 43.82,41.18 43.97,41.33 RB42.1
V_M_BMC_DDR3_RST_N: length 64.3
  TOP w0.104: v1(42.55,46.36) 42.55,47.13 43.1,47.68 RB23.1
  TOP w0.112: UT7.V28 31.98,30.76 31.29,31.45 28.72,31.45 27.96,32.21 17.44,32.21 v1(16.91,31.68)
  TOP w0.127: U3.T2 v1(32.77,46.41) ; U2.T2 v1(22.93,46.43) ; U4.T2 v1(42.55,46.36)
  L8-SIG w0.076: v1(16.91,31.68) 16.91,32.49 16.02,33.38 16.02,45.75 16.33,46.06 18.33,46.06 19.08,46.81 22.55,46.81 v1(22.93,46.43)
  L10-SIG w0.076: v1(22.93,46.43) 23.37,46.87 32.31,46.87 v1(32.77,46.41) 33.24,46.87 42.04,46.87 v1(42.55,46.36)
V_M_BMC_DDR3_WE_N: length 57.9
  TOP w0.127: U3.L3 v1(31.97,42.41) ; UT7.E25 21.2,27.98 v1(21.2,28.03) ; U4.L3 v1(41.75,42.36) ; U2.L3 v1(22.13,42.43)
  L8-SIG w0.076: v1(21.2,28.03) 21.2,27.69 21.3,27.59 23.03,27.59 23.21,27.77 23.21,29.86 22.97,30.1 20.95,30.1 20.57,30.49 20.57,31.02 21.53,31.98 21.92,31.98 22.04,32.1 22.04,32.58 22.15,32.7 22.38,32.7 22.49,32.58 22.49,32.1 22.61,31.98 23.13,31.98 23.34,32.19 23.34,35.53 23.45,35.64 24.26,35.64 24.38,35.76 24.38,36.34 24.26,36.45 23.45,36.45 23.34,36.57 23.34,37.1 23.45,37.22 24.03,37.22 24.15,37.33 24.15,37.94 24.03,38.05 23.45,38.05 23.34,38.17 23.34,38.73 23.45,38.84 24.01,38.84 24.15,38.98 24.15,39.62 24.01,39.76 23.45,39.76 23.34,39.87 23.34,41 23.11,41.23 21.91,41.23 21.71,41.43 21.71,42.01 v1(22.13,42.43) 22.52,42.03 31.6,42.03 v1(31.97,42.41) 32.39,41.99 41.37,41.99 v1(41.75,42.36)
  BOTTOM w0.112: RB7.1 40.1,47.68 40.4,47.38 40.4,43.21 41.01,42.59 41.02,42.59 41.25,42.36 v1(41.75,42.36)
V_M_BMC_DDR3_ZQ_0: length 1.6
  TOP w0.127: U2.L8 v1(17.33,42.43)
  BOTTOM w0.112: RB44.1 17.75,42.13 17.62,42.13 v1(17.33,42.43)
V_M_BMC_DDR3_ZQ_1: length 1.6
  TOP w0.127: U3.L8 v1(27.17,42.41)
  BOTTOM w0.112: v1(27.17,42.41) 27.55,42.02 27.64,42.02 RB43.1
V_M_BMC_DDR3_ZQ_2: length 1.6
  TOP w0.127: U4.L8 v1(36.95,42.36)
  BOTTOM w0.112: RB45.1 37.31,42 37.31,42.01 v1(36.95,42.36)
VR_FET_SW_P3V3_AUX_P1V1_AUX: length 1.8
  TOP w0.203: UT6.13 12.27,22.91 12.16,23.02 v2(12.16,23.05) ; UT6.14 11.82,22.57 11.4,22.99 v2(11.4,23.02)
VR_FET_SW_P3V3_AUX_P1V2_AUX: length 1.2
  BOTTOM w0.127: v1(51.76,16.59) 51.73,16.59 51.17,16.03 50.77,16.03
  vias: v1(52.29,16.62)
VR_FET_SW_P3V3_AUX_P1V8_AUX:
  vias: v1(65.05,11.46) v1(65.08,10.93)
VR_FET_SW_P12V_AUX_P1V5_AUX: length 2
  TOP w0.254: v2(2.63,20.88) 2.91,20.88 3.02,20.99 UT5.18 ; UT5.17 2.89,21.49 v2(2.63,21.75)
VR_FET_SW_P12V_AUX_P2V5_AUX: length 3
  TOP w0.254: v2(2.25,16.03) 2.63,16.03 2.77,15.9 UT8.17 ; v2(1.87,15.4) v2(2.63,15.4) 2.87,15.4 2.88,15.4 UT8.18
VR_P0V75_AUX_REFIN: length 2.7
  BOTTOM w0.254: EU8F1.1 49.88,42.91 50.01,43.03 R8F5.1 C8F4.1 R8F3.2
VR_P0V75_AUX_SENSE: length 1.3
  BOTTOM w0.254: EU8F1.5 46.42,42.14 R8F1.1
VR_P0V75_AUX_VIN: length 1.7
  BOTTOM w0.254: C8F5.1 49.79,45.6 49.71,45.67 EU8F1.10
VR_P1V1_AUX_EN: length 1.2
  TOP w0.203: RT67.2 13.17,19.05 UT6.4
VR_P1V1_AUX_FB: length 2.3
  TOP w0.203: RT64.1 RT65.2 12.27,19.51 UT6.2
VR_P1V1_AUX_FB_R: length 1.6
  TOP w0.508: RT65.1 11.68,17.87 v2(11.68,17.37)
  BOTTOM w0.508: v2(11.68,17.37) 11.68,17.54 11.97,17.83 RB113.2
VR_P1V2_AUX_EN: length 2
  TOP w0.254: v1(52.83,13.47) 52.83,13.8 53.03,14 UT9.5
  BOTTOM w0.254: RB128.2 52.8,13.49 v1(52.83,13.47)
VR_P1V2_AUX_FB: length 1.8
  TOP w0.254: v1(54.2,16.29) 54.07,16.16 54.07,16.03 53.98,15.94 UT9.9
  BOTTOM w0.254: v1(54.2,16.29) RB121.1 RB124.2
VR_P1V2_AUX_FB_R: length 0.8
  BOTTOM w0.254: RB124.1 RB129.2
VR_P1V5_AUX_EN: length 2
  TOP w0.254: UT5.11 5.44,23.6 5.75,23.91 RT51.2
VR_P1V5_AUX_FB: length 2.5
  TOP w0.254: v2(4.54,23.42) 4.54,23.27 4.64,23.17 UT5.13
  BOTTOM w0.381: v2(4.54,23.42) 4.68,23.56 RB80.1
  BOTTOM w0.508: v2(4.54,23.42) 4.54,23.4 4.6,23.34 RB93.2
VR_P1V5_AUX_FB_R: length 0.8
  BOTTOM w0.508: RB92.2 RB93.1
VR_P1V8_AUX_EN: length 1.8
  TOP w0.254: UT11.5 63.12,10.32 63.85,10.32 v1(64.05,10.52)
  BOTTOM w0.254: v1(64.05,10.52) 63.8,10.78 RB141.2
VR_P1V8_AUX_FB: length 2.1
  TOP w0.254: UT11.9 64.62,9.34 64.69,9.28 v1(65.22,9.28)
  BOTTOM w0.254: v1(65.22,9.28) 65.06,9.28 64.84,9.49 RB155.1 63.85,9.49 RB156.2
VR_P1V8_AUX_FB_R: length 0.8
  BOTTOM w0.254: RB156.1 RB157.2
VR_P2V5_AUX_EN: length 1
  TOP w0.254: UT8.11 5.44,17.69 5.49,17.75 5.49,17.94 RT62.2
VR_P2V5_AUX_FB: length 3.2
  TOP w0.254: v2(3.8,17.86) v2(4.46,17.86) 4.64,17.68 UT8.13
  BOTTOM w0.254: RB117.2 RB114.1 4.79,18.19 v2(4.46,17.86)
VR_P2V5_AUX_FB_R: length 1.1
  BOTTOM w0.508: RB117.1 6.38,17.18 RB120.2
XTAL_SI5351_XA: length 7.2
  TOP w0.104: YT1.1 48.62,16.53 47.77,15.68 47.77,14.33 47.92,14.18 48.11,14.18 48.54,13.75 C5C5.1 49.56,13.11 R5C3.1 49.82,12.06 49.99,11.88 EU5C1.1
XTAL_SI5351_XB: length 5.6
  TOP w0.104: EU5C1.2 49.49,11.98 48.61,12.86 R5C3.2 48.42,13.55 48.22,13.75 C5C6.1 47.78,13.99 47.54,14.24 47.54,14.71 47.32,14.93 YT1.3
XTAL_USBPHY_PCH_24M_IN: length 8
  TOP w0.112: Y7A1.1 64.31,14.37 63.49,13.54 61.47,13.54 61.12,13.9 60.45,13.9 60.37,13.97 60.37,14.32 C7A17.1 59.97,14.1 58.94,14.1 58.83,13.99 58.83,13.93 58.83,13.92 58.83,13.88 58.63,13.68 R7A57.1 58.63,13.2 58.49,13.07 U8A6.26
XTAL_USBPHY_PCH_24M_OUT: length 4.5
  TOP w0.104: U8A6.25 59,12.95 59.02,12.98 59.02,13.07 59.52,13.57 R7A57.2
  TOP w0.112: R7A57.2 60.97,13.65 61.27,13.34 C7A16.1 62.13,12.91 Y7A1.3
XTAL_USBPHY_USB2B_24M_IN: length 6.5
  TOP w0.104: Y2.1 66.49,20.34 65.56,21.27 C307.1
  TOP w0.112: EU12.26 61.44,21.01 61.57,21.14 63.06,21.14 63.11,21.19 63.26,21.19 63.39,21.33 R398.1 63.54,21.54 65.36,21.54 C307.1
XTAL_USBPHY_USB2B_24M_OUT: length 5.3
  TOP w0.112: C306.1 64.47,18.73 Y2.3 63.7,19.52 63.7,20.22 63.42,20.5 R398.2 63.37,20.53 62.99,20.53 62.63,20.88 62.17,20.88 61.94,20.65 EU12.25

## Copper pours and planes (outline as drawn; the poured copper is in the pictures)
AGND_ADC on L6-VCC: 62.44,25.91 62.44,31.49 62.78,31.83 67.66,31.83 67.66,31.81 67.79,31.68 67.79,25.46 67.66,25.33 63.04,25.33 62.45,25.91
GND on TOP: 64.61,10.57 66.52,10.57 66.64,10.44 66.64,9.05 66.52,8.92 65.12,8.92 64.36,9.68 64.36,10.32
GND on BOTTOM: 11.91,10.83 12.41,10.83 12.79,10.44 12.79,10.32 12.92,10.19 14.95,10.19 15.21,9.94 15.21,7.4 14.83,7.02 12.03,7.02 11.78,7.27 11.78,10.7
GND on BOTTOM: 2.63,17.81 3.22,17.81 3.85,17.18 4.79,17.18 4.92,17.05 4.92,16.41 4.79,16.29 2.76,16.29 2.25,16.79 2.25,17.43
GND on BOTTOM: 5.33,13.04 6.9,13.04 7.13,12.81 7.13,9.68 6.72,9.28 4.67,9.28 4.49,9.45 4.49,10.29 4.44,10.34 4.03,10.34 3.96,10.42 3.96,11.56 4.01,11.61 5.02,11.61 5.2,11.79 5.2,12.91
GND on BOTTOM: 8.1,16.67 14.32,16.67 15.21,15.78 18.13,15.78 18.26,15.65 18.26,13.75 17.62,13.11 14.06,13.11 13.81,12.86 12.79,12.86 12.16,13.49 12.16,13.87 12.03,14 10.64,14 10.25,14.38 7.84,14.38 7.71,14.51 7.71,16.29
GND on BOTTOM: 59.28,12.55 59.28,8.54 57.58,8.54 57.55,8.51 55.7,8.51 55.39,8.82 55.39,12.3 55.64,12.55
GND on L2-GND, L4-GND, L9-GND, L11-GND: 0.51,49.49 69.09,49.49 69.09,22.51 68.5,22.51 67.68,22.17 67.34,21.35 67.34,18.65 67.68,17.83 68.5,17.49 69.09,17.49 69.09,0.51 39.31,0.51 39.31,3.5 38.3,4.51 37.29,3.5 37.29,0.51 0.51,0.51 0.51,17.49 1.1,17.49 1.92,17.83 2.26,18.65 2.26,21.35 1.92,22.17 1.1,22.51 0.51,22.51
P0V75_AUX on BOTTOM: 33.78,49.31 43.83,49.31 44.16,48.98 44.16,48.42 44.06,48.32 33.83,48.32 33.67,48.47 33.67,49.21
P0V75_AUX on L10-SIG: 33.57,49.49 47.34,49.49 48.71,48.12 48.71,42.28 48.7,42.28 48.7,39.75 48.23,39.27 45.89,39.27 45.76,39.4 45.76,42 45.69,42.08 45.69,42.93 44.7,43.92 44.7,46.59 43.33,47.96 33.88,47.96 33.57,48.27
P0V75_AUX_REFOUT on L7-VCC: 37.86,29.22 33.17,29.22 32.53,28.58 32.53,24.34 32.1,23.91 30.24,23.91 29.89,24.26 29.89,28.48 29.53,28.83 24.86,28.83 24.63,28.61 24.63,27.39 23.92,26.68 22.42,26.68 21.96,27.13 17.27,27.13 15.36,29.04 15.36,45.75 16.94,47.33 43.4,47.33 43.41,47.31 46.23,47.31 46.75,46.79 46.75,38.11
P1V1_AUX on TOP: 13.43,22.76 14.57,22.76 14.95,22.38 16.22,22.38 16.35,22.26 16.35,21.49 15.84,20.99 13.56,20.99 13.43,21.11
P1V1_AUX on BOTTOM: 15.72,18.95 17.37,18.95 17.49,18.83 17.49,16.16 17.37,16.03 16.1,16.03 15.46,16.67 15.46,18.7
P1V1_AUX on BOTTOM: 30.6,29.29 31.95,29.29 32.1,29.14 32.1,24.97 31.62,24.49 30.63,24.49 30.37,24.75 30.37,29.06
P1V1_AUX on BOTTOM: 14.57,22.64 15.59,22.64 16.01,22.22 16.24,22.22 16.5,21.95 16.5,21.14 15.72,20.35 12.97,20.35 12.95,20.38 12.95,21.32 13.05,21.42 13.53,21.42 13.54,21.41 13.98,21.41 14.32,21.75 14.32,22.38
P1V1_AUX on BOTTOM: 29.84,18.8 30.09,18.8 30.83,18.06 30.83,12.27 30.52,11.97 28.7,11.97 28.29,12.38 28.29,13.06 28.11,13.24 25.42,13.24 24.15,14.51 24.15,18.12 24.83,18.8 24.83,22.36 25.57,23.09 28.44,23.09 29.84,21.7
P1V1_AUX on L5-SIG: 31.46,24.47 31.46,20.43 30.19,19.16 30.19,16.77 30.09,16.67 27.35,16.67 27.27,16.74 27.27,21.93 27.63,22.28 29.66,22.28 29.76,22.18 30.19,22.18 30.3,22.28 30.3,23.4 30.02,23.68 29.69,23.68 29.51,23.86 29.51,24.41 30.12,25.02 30.91,25.02
P1V1_AUX on L6-VCC: 14.9,23.4 17.24,23.4 17.6,23.04 22.75,23.04 23.29,23.58 28.26,23.58 28.75,23.09 28.75,21.04 29.38,20.4 30.7,20.4 31.01,20.1 31.01,14.18 30.08,13.25 23.22,13.25 22.95,13.52 22.95,14 22.37,14.59 15.11,14.59 15.08,14.61 12.82,14.61 11.8,15.63 11.8,17.58 12.08,17.86 15.28,17.86 15.82,18.4 15.82,20.73 15.26,21.29 14.83,21.29 14.62,21.49 14.62,23.12
P1V1_AUX_VCCEGXB on L7-VCC: 26.51,12.6 30.52,12.6 31.08,12.05 31.08,11 30.96,10.88 26.71,10.88 26.43,11.16 26.43,12.53
P1V1_AUX_VCCLGXB on BOTTOM: 31.06,13.16 32.18,13.16 32.4,12.93 32.61,12.93 32.91,12.63 32.91,10.11 32.4,9.61 32.4,9.15 30.96,7.7 26.56,7.7 25.75,8.51 25.75,9.96 26.46,10.67 30.09,10.67 30.93,11.51 30.93,13.04
P1V2_AUX on TOP: 53.54,15.55 54.5,15.55 54.7,15.75 55.54,15.75 55.62,15.68 55.62,14.84 55.8,14.66 56.56,14.66 56.61,14.61 56.61,14.08 56.48,13.95 56.48,13.92 55.77,13.92 55.75,13.95 54.76,13.95 54.5,13.7 53.82,13.7 53.51,14 53.51,15.52
P1V2_AUX on BOTTOM: 56.66,37.09 57.65,37.09 57.93,36.81 57.93,35.13 57.6,34.8 57.6,34.19 57.88,33.91 59.15,33.91 59.38,33.69 59.38,31.02 59.78,30.61 59.78,29.57 59.33,29.11 58.72,29.11 57.8,30.03 57.8,30.59 57.45,30.94 55.82,30.94 55.52,30.64 55.52,29.85 55.39,29.72 55.01,29.72 54.88,29.85 54.88,31.17 54.93,31.22 54.32,31.22 54.07,30.97 54.07,30.84 53.74,30.84 53.74,33.23 53.99,33.48 53.99,34.63 54.25,34.88 55.87,34.88 56.33,35.34 56.33,36.76
P1V2_AUX on L6-VCC: 59.43,20 59.02,19.59 57.65,19.59 57.12,19.06 57.12,17.68 57.31,17.49 57.31,15.72 56.74,15.14 56.74,14.08 56.33,13.67 52.85,13.67 51.75,14.78 51.75,20.29 52.57,21.11 52.72,21.11 52.72,30.05 53.51,30.84 58.59,30.84 59.43,30
P1V2_AUX on L10-SIG: 58.29,26.12 44.75,26.12 44.06,25.43 44.06,25.1 43.91,24.95 43.3,24.95 43.02,25.23 43.02,28.43 44.9,30.31 46.86,30.31 46.86,30.3 49.63,30.3 51.77,32.44 51.77,32.45 54.2,34.88 59.51,34.88 59.84,34.55 59.84,27.67
P1V2_AUX_PLL on L6-VCC: 59.68,27.46 59.68,28.68 59.18,29.19 52.98,29.19 52.37,28.58 52.37,27.56 52.01,27.21 49.4,27.21 49.14,27.46 49.14,35.54 50.49,36.89 60.85,36.89 62.15,35.59 62.15,27.54 61.72,27.11 60.04,27.11
P1V5_AUX on TOP: 6.57,24.03 7.05,24.03 7.87,24.85 10.03,24.85 10.38,24.49 10.38,22.26 9.87,21.75 6.32,21.75 6.06,22 6.06,23.53
P1V5_AUX on BOTTOM: 49.02,42.07 49.02,40.47 49.12,40.37 50.01,40.37 50.08,40.44 50.08,41.92 49.8,42.19 49.24,42.19 48.96,42.47 48.76,42.47 48.71,42.42 48.71,42.37
P1V5_AUX on BOTTOM: 6.83,24.41 7.59,24.41 7.97,24.8 9.42,24.8 9.75,24.47 9.75,22.26 9.49,22 7.08,22 6.7,22.38 6.7,24.29
P1V5_AUX on L6-VCC: 40.56,28.48 38.19,26.12 35.15,26.12 34.89,25.86 34.61,25.86 34.36,25.61 34.36,21.47 33.88,20.99 33.06,20.99 32.63,20.55 31.39,20.55 30.6,21.34 30.12,21.34 29.27,22.19 29.27,23.87 28.92,24.21 23.92,24.21 23.11,23.4 18.51,23.4 18.09,23.82 14.83,23.82 14.48,23.48 7.64,23.48 7.51,23.6 7.51,25 7.79,25.28 7.82,25.28 7.82,25.53 8.53,26.24 8.53,27.51 9.11,28.1 12.54,28.1 13.05,28.61 13.05,36.12 11.96,37.22 11.96,38.16 12.06,38.26 12.06,39.22 12.03,39.25 12.03,42.37 12.06,42.37 16.35,46.67 46.73,46.67 50.18,43.21 50.18,40.19 49.83,39.83 46.07,39.83 45.33,39.1 45.33,33.1 43.86,31.63 43.86,29.62 42.72,28.48
P1V8_AUX on TOP: 64.1,9.81 64.23,9.68 64.23,8.92 64.1,8.79 63.72,8.79 63.59,8.67 63.59,7.65 63.34,7.4 62.32,7.4 62.2,7.52 62.2,9.68 62.32,9.81
P1V8_AUX on L10-SIG: 56.91,23.09 62.68,23.09 63.52,22.26 63.52,9.51 62.55,8.54 61.64,8.54 60.98,9.2 60.98,11.56 59.07,13.47 59.07,14.56 59.3,14.79 61.36,14.79 61.56,14.99 61.56,20.33 61.87,20.63 61.87,21.85 61.39,22.33 59.48,22.33 59.45,22.31 56.99,22.31 56.76,22.54 56.76,22.92 56.91,23.07
P1V8_P3V3_GPPA_AUX on BOTTOM: 13.96,32.75 15.06,32.75 15.36,32.44 15.36,27.29 15.21,27.13 13.86,27.13 13.48,27.51 13.48,30.13 13.86,30.51 13.86,32.64
P1V8_P3V3_GPPA_AUX on L7-VCC: 32.38,14.64 33.85,14.64 35.22,13.26 35.22,4.22 33.65,2.65 13.4,2.65 13.4,2.67 12.85,2.67 10.41,5.11 10.41,7.09 11.45,8.13 11.47,8.13 12.49,9.15 24.89,9.15 26.16,10.42 31.34,10.42 31.9,10.98 31.9,14.15
P1V8_P3V3_GPPA_AUX on L8-SIG: 1.77,32.95 14.32,32.95 15.11,32.16 15.11,27.95 14.95,27.79 1.75,27.79 1.42,28.12 1.42,32.59
P1V8_P3V3_GPPA_AUX on L10-SIG: 2.48,32.14 2.84,31.78 2.84,30.61 6.83,26.62 6.83,10.22 9.52,7.52 11.88,7.52 12.57,6.84 12.57,1.61 11.98,1.02 2.66,1.02 0.68,3 0.68,17.49 1.1,17.49 1.92,17.83 2.26,18.65 2.26,21.35 1.92,22.17 1.1,22.51 0.68,22.51 0.68,31.86 0.96,32.14 ; 2 cut-outs
P2V5_AUX on TOP: 6.95,18.7 9.75,18.7 10,18.45 10,16.67 9.49,16.16 6.19,16.16 6.06,16.29 6.06,17.05 6.7,17.68 6.7,18.45
P2V5_AUX on BOTTOM: 61.97,25.18 61.97,24.08 62.27,23.78 62.83,23.78 62.93,23.88 62.93,25.13 62.88,25.18
P2V5_AUX on BOTTOM: 24.86,28.53 29,28.53 29.76,27.77 29.76,24.39 31.26,24.39 32.2,23.45 32.2,19.11 31.95,18.85 31.08,18.85 30.98,18.95 30.98,19.28 31.01,19.31 31.01,21.39 29.05,23.35 24.86,23.35 24.83,23.37 24.83,24.03 25.16,24.03 25.72,24.59 25.72,25.74 25.34,26.12 24.81,26.12 24.71,26.22 24.71,28.38
P2V5_AUX on BOTTOM: 7.97,18.83 10.13,18.83 10.38,18.57 10.38,17.05 10.13,16.79 7.84,16.79 7.59,16.54 7.59,16.03 6.95,16.03 6.95,17.81
P2V5_AUX on L7-VCC: 25.27,28.02 29.36,28.02 29.64,27.74 29.64,24.03 29.2,23.6 25.44,23.6 25.42,23.63 21.1,23.63 20.44,22.97 17.65,22.97 11.58,16.9 7.31,16.9 6.9,17.3 6.9,20.99 8.58,22.66 9.65,22.66 9.65,46 12.85,49.21 56.61,49.21 62.99,42.83 62.99,23.6 62.76,23.37 59.89,23.37 59.3,23.96 59.3,27.82 58.82,28.3 52.37,28.3 52.06,28.61 52.06,45.7 50.21,47.55 16.58,47.55 14.7,45.67 14.7,29.06 17.52,26.24 24.38,26.24 24.86,26.73 24.86,27.62
P2V5_AUX_FILT on BOTTOM: 21.86,25.02 22.8,25.02 23.03,25.25 23.51,24.77 23.51,24.11 23.69,23.93 23.97,23.93 24.33,23.58 24.33,19.72 23.72,19.11 23.72,16.97 24.07,16.62 24.07,13.42 23.82,13.16 21.86,13.16 20.9,14.13 20.9,20.27 21.08,20.45 21.61,20.45 21.74,20.58 21.74,24.9
P2V5_AUX_FILT on L6-VCC: 20.44,14.13 22.17,14.13 22.42,13.87 22.42,13.44 22.95,12.91 30.5,12.91 31.39,13.8 31.39,20.1 31.59,20.3 34.03,20.3 34.74,21.01 34.74,22.21 34.69,22.26 34.69,24.95 34.82,25.08 36.57,25.08 38.09,23.55 38.09,10.65 36.24,8.79 21.48,8.79 20.03,10.24 20.03,13.72
P2V5_AUX_FILT on L10-SIG: 21.79,26.14 24.38,26.14 24.68,25.84 24.68,24.41 24.61,24.34 21.74,24.34 21.51,24.57 21.51,25.86
P2V5_AUX_VCCADC on BOTTOM: 63.29,25.15 63.29,23.48 63.49,23.27 64.13,23.27 64.15,23.3 64.15,24.57 64.1,24.62 64.1,25.1 64.05,25.15
P2V5_AUX_VCCADC on L10-SIG: 67.61,30.71 64.84,30.71 64.41,30.28 60.67,30.28 60.22,29.83 60.22,28.17 63.37,25.02 63.37,23.55 63.54,23.37 63.95,23.37 64.41,23.83 64.41,24.49 64.86,24.95 67.28,24.95 67.71,25.38 67.71,30.61
P3V3_AUX on BOTTOM: 2.53,10.27 4.41,10.27 4.46,10.22 4.46,9.28 4.36,9.17 2.66,9.17 2.46,9.38 2.46,10.19
P3V3_AUX on BOTTOM: 13.33,24.8 13.94,24.8 14.19,24.54 14.19,23.4 13.94,23.14 12.79,23.14 12.29,23.65 11.78,23.65 11.65,23.78 11.65,24.67 11.19,25.13 11.19,29.29 11.32,29.42 12.19,29.42 12.97,28.63 12.97,25.15
P3V3_AUX on BOTTOM: 51.3,47.3 50.97,47.3 50.84,47.43 50.84,49.31 51,49.46 51.81,49.46 51.96,49.31 51.96,49.05 51.43,48.52 51.43,47.43
P3V3_AUX on L3-SIG: 7.87,13.11 9.52,13.11 10.86,11.77 10.86,6.43 10.38,5.95 8.71,5.95 7.66,6.99 7.66,12.91
P3V3_AUX on L6-VCC, L7-VCC: 0.51,49.49 69.09,49.49 69.09,22.51 68.5,22.51 67.68,22.17 67.34,21.35 67.34,18.65 67.68,17.83 68.5,17.49 69.09,17.49 69.09,0.51 39.31,0.51 39.31,3.5 38.3,4.51 37.29,3.5 37.29,0.51 0.51,0.51 0.51,17.49 1.1,17.49 1.92,17.83 2.26,18.65 2.26,21.35 1.92,22.17 1.1,22.51 0.51,22.51
P3V3_AUX_EDGE on BOTTOM: 2.08,8.67 4.31,8.67 4.46,8.51 4.46,7.47 4.31,7.32 2.46,7.32 2.03,7.75 2.03,8.62
P3V3_AUX_EDGE on L7-VCC: 1.92,9.35 7.23,9.35 7.56,9.02 7.56,3.05 7.03,2.52 1.97,2.52 1.57,2.93 1.57,9
P3V3_AUX_IO on BOTTOM: 21.66,25.86 22.7,25.86 22.85,25.71 22.85,25.2 22.73,25.08 21.74,25.08 21.48,24.82 21.48,21.62 21.76,21.34 22.19,21.34 22.24,21.29 22.24,20.63 22.19,20.58 20.54,20.58 19.93,21.19 19.93,23.42 19.75,23.6 19.3,23.6 19.22,23.68 19.22,25.33 19.78,25.89 21.63,25.89
P3V3_AUX_IO on L7-VCC: 32.96,27.79 33.42,28.25 42.54,28.25 44.93,30.64 44.93,32.72 45.08,32.87 51.56,32.87 51.66,32.77 51.66,28.4 52.14,27.92 58.44,27.92 58.81,27.55 58.81,24.1 49.74,15.03 45.52,15.03 40.48,9.99 37.08,9.99 35.73,11.33 35.73,14.13 35.03,14.83 35.03,14.93 34.92,15.04 31.59,15.04 31.31,14.76 31.31,13.01 31.11,12.81 29.13,12.81 29.08,12.86 25.77,12.86 25.57,12.66 25.57,10.52 24.48,9.43 11.4,9.43 11.26,9.29 9.96,9.29 9.54,9.71 5.23,9.71 3.09,11.84 3.09,22.26 1.34,24.01 1.34,27.77 1.8,28.22 7.56,28.22 8.6,27.18 8.6,23.3 6.6,21.29 6.6,17.1 7.33,16.36 11.7,16.36 17.77,22.43 17.77,22.66 20.59,22.66 21.39,23.46 21.41,23.45 32.25,23.45 32.96,24.16
P3V3_AUX_IO on L8-SIG: 61.44,37.65 52.37,37.65 51.23,36.51 51.23,27.87 51.83,27.26 56.56,27.26 58.9,24.92 58.9,21.14 59.1,20.94 61.69,20.94 61.84,21.09 61.84,37.24
P3V3_AUX_M10_VCCIO1A on BOTTOM: 59.61,32.92 61.21,32.92 61.51,33.23 62.05,33.23 62.12,33.15 62.12,30.92 62.07,30.87 61.46,30.87 60.55,31.78 59.76,31.78 59.56,31.98 59.56,32.87
P3V3_SI5338_AUX on L7-VCC: 45.64,11.94 52.77,11.94 53.13,11.59 53.13,6.61 51.73,5.21 46.17,5.21 45.1,6.28 45.1,11.41
P3V3_USBPHY_AUX on L5-SIG: 55.62,15.25 57.65,15.25 58.62,14.28 59,14.28 59,8.77 59.56,8.21 59.56,7.22 58.92,6.58 55.29,6.58 54.07,7.8 54.07,13.7 ; 1 cut-out
P3V3_USBPHY_USB2B_AUX on L8-SIG: 58.26,21.14 57.6,21.14 56.86,20.4 56.86,15.8 57.98,14.69 61.31,14.69 61.72,15.09 61.72,19.64 61.33,20.02 59.38,20.02
P5V_USBPHY_AUX on BOTTOM: 60.8,9.23 61.44,9.23 61.54,9.33 61.92,9.33 62.2,9.05 62.2,7.02 61.94,6.76 60.93,6.76 60.62,7.07 60.62,8.97 60.8,9.15
P12V_AUX on BOTTOM: 4.41,12.93 4.46,12.88 4.46,11.84 4.36,11.74 2.25,11.74 2.2,11.79 2.2,12.81 2.33,12.93
P12V_AUX on BOTTOM: 5.3,20.73 8.86,20.73 9.49,20.1 9.49,19 9.32,18.83 7.92,18.83 7.54,19.21 5.56,19.21 5.3,19.46
P12V_AUX on L3-SIG: 2.48,21.01 8.05,21.01 9.44,19.61 9.44,17.56 4.34,12.45 4.34,7.73 4.67,7.4 6.83,7.4 6.95,7.27 6.95,6.43 6.62,6.1 6.62,6.08 6.32,5.77 0.94,5.77 0.51,6.2 0.51,16.09 2.48,18.06
P12V_AUX_EDGE on TOP: 1.11,3.59 1.11,0.54 1.19,0.46 1.57,0.46 1.59,0.49 1.59,3.18 2.89,4.48 4.29,4.48 4.3,4.49 4.78,4.49 5.1,4.81 5.1,6.74 4.97,6.86 3.88,6.86 3.65,6.63 3.65,5.54 3.24,5.54 3.04,5.34 3.04,5.14 2.89,4.98 2.51,4.98
RST_HPS_PORBTN__R_N on TOP: 4.41,36.35 4.54,36.23 4.54,33.3 4.16,32.92 4.16,31.91 3.9,31.65 3.65,31.65 3.52,31.78 3.52,32.92 3.78,33.18 3.78,34.19 3.65,34.32 2,34.32 1.95,34.37 1.95,36.28 2.03,36.35
VR_FET_SW_P3V3_AUX_P1V1_AUX on BOTTOM: 10.38,23.14 11.14,23.14 11.27,23.27 12.29,23.27 12.79,22.76 13.94,22.76 14.06,22.64 14.06,21.8 13.89,21.62 12.77,21.62 12.67,21.52 12.67,20.53 12.48,20.34 10.9,20.34 10.13,21.11 10.13,22.89
VR_FET_SW_P3V3_AUX_P1V2_AUX on TOP: 50.46,16.97 52.24,16.97 52.5,16.72 52.5,16.44 52.57,16.36 52.57,15.75 52.5,15.68 50.41,15.68 50.29,15.8 50.29,16.79
VR_FET_SW_P3V3_AUX_P1V2_AUX on BOTTOM: 50.18,17 52.29,17 52.6,16.69 52.6,15.83 52.24,15.47 50.13,15.47 50.06,15.55 50.06,16.87
VR_FET_SW_P3V3_AUX_P1V8_AUX on TOP: 64.23,10.95 64.23,12.1 64.36,12.22 66.39,12.22 66.52,12.1 66.52,10.95 66.39,10.83 64.36,10.83
VR_FET_SW_P3V3_AUX_P1V8_AUX on BOTTOM: 64.36,12.86 64.99,12.86 65.25,13.11 66.39,13.11 66.52,12.98 66.52,11.21 66.13,10.83 64.48,10.83 64.36,10.95
VR_FET_SW_P12V_AUX_P1V5_AUX on BOTTOM: 2.13,23.27 2.89,23.27 3.27,22.89 3.27,22.26 3.52,22 5.05,22 5.17,21.87 5.17,19.59 4.67,19.08 3.78,19.08 3.65,19.21 3.65,20.22 3.4,20.48 2.51,20.48 2.38,20.6 2.38,21.75 2,22.13 2,23.14
VR_FET_SW_P12V_AUX_P2V5_AUX on BOTTOM: 6.19,14.89 6.19,13.37 6.06,13.24 2.63,13.24 1.49,14.38 1.49,15.91 1.87,16.29 2.51,16.29 2.76,16.03 5.05,16.03
VR_P0V75_AUX_VIN on BOTTOM: 49.12,45.42 50.54,45.42 50.67,45.29 51.23,45.29 51.35,45.42 51.35,46.67 51.25,46.77 50.82,46.77 50.08,46.03 49.24,46.03 49.09,45.88 49.09,45.45
